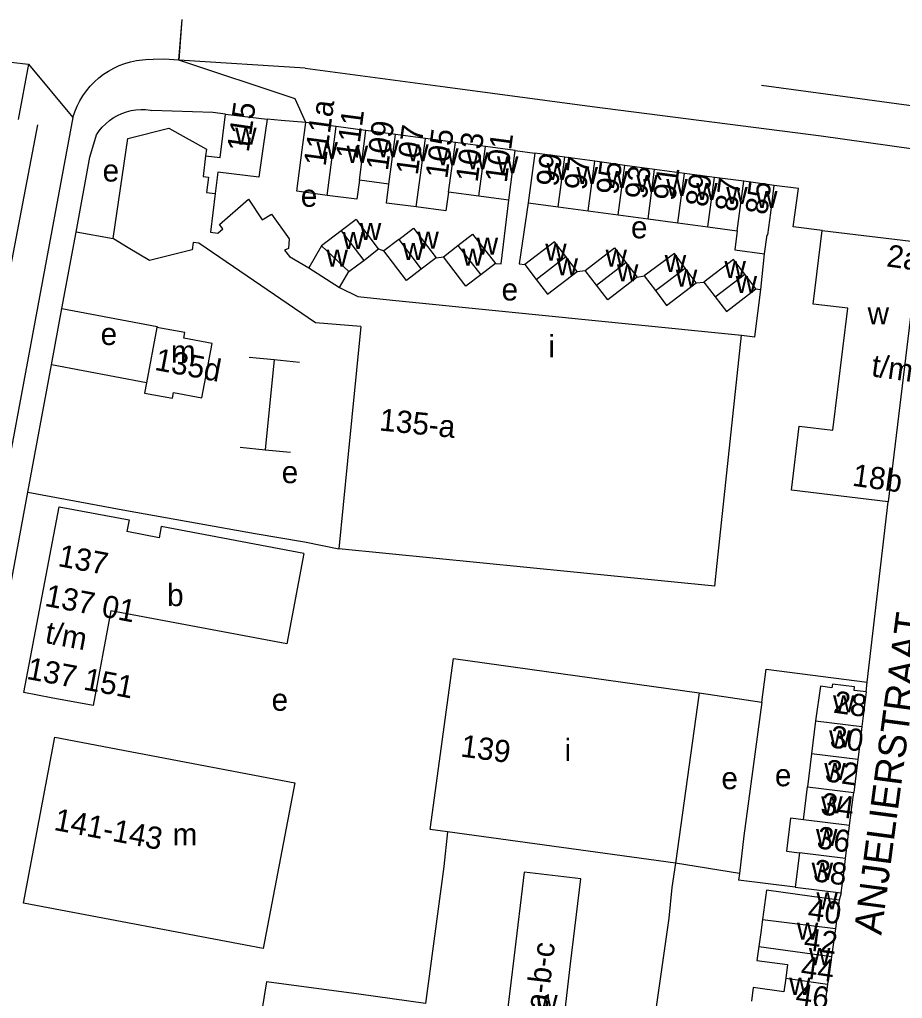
# Model space of a CAD drawing. Extents: x 161258 to 163262, y 380749 to 382054.
# Drawn here: x 161839.1 to 161998.1, y 381470.7 to 381647.1 of the extents above; entities that cross this region are included whole.
import ezdxf

# ---------------------------------------------------------------- set-up
doc = ezdxf.new("R2010")
doc.units = 0
for name, color, linetype in [('BLT_Basislijn', 7, 'Continuous'), ('BLT_Bebouwing', 7, 'Continuous'), ('BLT_Centroide', 7, 'Continuous'), ('BLT_Huisnummer', 7, 'Continuous'), ('BLT_Huisnummer_ tussenligend', 7, 'Continuous'), ('BLT_Huisnummer_reeks', 7, 'Continuous'), ('BLT_Onderverdeling_panden', 7, 'Continuous'), ('BLT_Straatnaam', 7, 'Continuous'), ('BLT_Vlakafsluiter', 7, 'Continuous')]:
    doc.layers.add(name, color=color, linetype=linetype)

msp = doc.modelspace()

# ---------------------------------------------------------------- linework, layer by layer
at = {"layer": 'BLT_Basislijn'}
for p, q in [((161865.19, 381639.93), (161863.15, 381639.92)), ((161867.69, 381639.77), (161865.19, 381639.93)), ((161867.74, 381639.77), (161867.69, 381639.77)), ((161890.5, 381638.33), (161867.74, 381639.77)), ((161848.67, 381629.43), (161829.26, 381525.22)), ((161886.18, 381628.93), (161883.71, 381629.14)), ((161890.62, 381628.56), (161886.18, 381628.93)), ((161928.39, 381623.47), (161931.92, 381622.99)), ((161983.65, 381609.07), (161978.46, 381609.76)), ((161846.7, 381595.04), (161849.25, 381608.8)), ((161855.92, 381607.61), (161849.25, 381608.8)), ((161903.77, 381605.76), (161904.72, 381605.42)), ((161914.13, 381604.18), (161915.43, 381604.36)), ((161972.63, 381598.47), (161973.31, 381604.89)), ((161939.52, 381601.72), (161940.95, 381601.89)), ((161950.37, 381600.65), (161951.59, 381600.92)), ((161960.99, 381599.65), (161962.38, 381599.78)), ((161971.54, 381589.91), (161972.63, 381598.47)), ((161971.73, 381598.55), (161972.63, 381598.47)), ((161844.82, 381584.89), (161846.7, 381595.04)), ((161969.13, 381590.24), (161971.54, 381589.91)), ((161840.57, 381561.92), (161844.82, 381584.89)), ((161880.44, 381586.28), (161884.97, 381585.82)), ((161884.97, 381585.82), (161883.35, 381569.58)), ((161884.97, 381585.82), (161889.51, 381585.37)), ((161878.8, 381570.03), (161883.35, 381569.58)), ((161883.35, 381569.58), (161887.88, 381569.12)), ((161991.81, 381527.74), (161995.59, 381560.22)), ((161972.82, 381524.14), (161973.56, 381530.03)), ((161973.56, 381530.03), (161991.81, 381527.74)), ((161961.49, 381525.82), (161972.82, 381524.14)), ((161968.77, 381493.27), (161957.23, 381495.12)), ((161968.77, 381493.27), (161968.62, 381492.02)), ((161978.81, 381490.77), (161968.62, 381492.02)), ((161987.12, 381489.74), (161986.76, 381488.41))]:
    msp.add_line(p, q, dxfattribs=at)
for points in [[(161848.67, 381629.43), (161849.02, 381630.46), (161849.43, 381631.46), (161849.92, 381632.42), (161850.48, 381633.34), (161851.11, 381634.23), (161851.8, 381635.06), (161852.55, 381635.84), (161853.36, 381636.56), (161854.21, 381637.22), (161855.11, 381637.81), (161856.06, 381638.34), (161857.04, 381638.79), (161858.05, 381639.17), (161859.09, 381639.48), (161860.14, 381639.71), (161861.21, 381639.86), (161862.29, 381639.93), (161863.15, 381639.92)], [(161890.62, 381628.56), (161888.74, 381632.82), (161867.74, 381639.77)], [(161837.52, 381639.39), (161840.71, 381639.08)], [(161840.71, 381639.08), (161838.84, 381629.11)], [(161890.5, 381638.33), (161915.74, 381634.98), (161942.21, 381631.45), (161983.51, 381626.15)], [(161972.76, 381635.24), (161986.51, 381633.39)], [(161986.51, 381633.39), (162033.24, 381627.05), (162058.66, 381624.22), (162070.84, 381623.16), (162081.43, 381622.63), (162093.08, 381622.28), (162119.5, 381621.62)], [(161852.95, 381626.31), (161853.43, 381627.04), (161853.98, 381627.71), (161854.59, 381628.33), (161855.25, 381628.9), (161855.96, 381629.4), (161856.72, 381629.83), (161857.51, 381630.19), (161858.33, 381630.48), (161859.18, 381630.69), (161860.04, 381630.83), (161860.91, 381630.88), (161861.78, 381630.86), (161862.64, 381630.75), (161862.88, 381630.71)], [(161876.17, 381630.06), (161873.92, 381630.32), (161862.88, 381630.71)], [(161787.91, 381344.08), (161804.27, 381430.36), (161834.23, 381585.88), (161842.37, 381628.14)], [(161849.25, 381608.8), (161851.74, 381622.31), (161852.95, 381626.31)], [(161983.51, 381626.15), (162038.53, 381618.39), (162049.65, 381617.33), (162066.6, 381615.74), (162081.96, 381614.86), (162104.2, 381614.33)], [(161978.46, 381609.76), (161979.39, 381616.68), (161975.04, 381617.22)], [(161924.81, 381603.15), (161925.85, 381603.05), (161927.2, 381614.54)], [(161930.72, 381614.07), (161929.11, 381603.08), (161930.12, 381602.97)], [(161846.7, 381595.04), (161863.84, 381591.81), (161863.8, 381591.63)], [(161861.95, 381581.66), (161844.82, 381584.89)], [(161821.19, 381474.73), (161830.92, 381509.79), (161840.57, 381561.92)], [(161840.57, 381561.92), (161858.34, 381558.67), (161881.51, 381554.51)], [(161881.51, 381554.51), (161890.39, 381553), (161896.59, 381551.76)], [(161991.58, 381525.98), (161991.81, 381527.74)], [(161972.82, 381524.14), (161969.58, 381500), (161968.77, 381493.27)], [(161916.15, 381500.72), (161915.53, 381494.51), (161912.22, 381469.83)], [(161957.23, 381495.12), (161956.61, 381490.71), (161956.07, 381485.21), (161949.07, 381436.37)]]:
    msp.add_lwpolyline(points, dxfattribs=at)
at = {"layer": 'BLT_Bebouwing'}
for p, q in [((161876.17, 381630.06), (161883.71, 381629.14)), ((161896.13, 381627.82), (161890.62, 381628.56)), ((161906.82, 381626.38), (161901.47, 381627.1)), ((161912.22, 381625.65), (161906.82, 381626.38)), ((161917.61, 381624.92), (161912.22, 381625.65)), ((161923, 381624.2), (161917.61, 381624.92)), ((161928.39, 381623.47), (161923, 381624.2)), ((161927.2, 381614.54), (161928.39, 381623.47)), ((161931.92, 381622.99), (161930.72, 381614.07)), ((161937.31, 381622.27), (161931.92, 381622.99)), ((161942.7, 381621.55), (161937.31, 381622.27)), ((161948.1, 381620.82), (161942.7, 381621.55)), ((161953.49, 381620.1), (161948.1, 381620.82)), ((161958.89, 381619.38), (161953.49, 381620.1)), ((161964.28, 381618.66), (161958.89, 381619.38)), ((161969.57, 381617.95), (161964.28, 381618.66)), ((161905.63, 381617.42), (161900.31, 381618.13)), ((161975.04, 381617.22), (161969.57, 381617.95)), ((161921.81, 381615.26), (161916.34, 381615.99)), ((161936.12, 381613.35), (161941.51, 381612.63)), ((161941.51, 381612.63), (161946.91, 381611.91)), ((161946.91, 381611.91), (161952.3, 381611.19)), ((161899.7, 381611.09), (161900, 381610.69)), ((161903.77, 381605.76), (161900, 381610.69)), ((161952.3, 381611.19), (161957.7, 381610.47)), ((161957.7, 381610.47), (161963.09, 381609.75)), ((161963.09, 381609.75), (161968.37, 381609.04)), ((161855.92, 381607.61), (161855.91, 381607.62)), ((161856, 381607.57), (161855.92, 381607.61)), ((161858.67, 381605.97), (161856, 381607.57)), ((161906.29, 381596.54), (161969.13, 381590.24)), ((161863.8, 381591.63), (161861.95, 381581.66)), ((161900.53, 381591.79), (161898.15, 381567.58)), ((161898.15, 381567.58), (161896.59, 381551.76)), ((161964.33, 381544.98), (161896.59, 381551.76)), ((161964.33, 381544.98), (161964.74, 381549.08)), ((161991.58, 381525.98), (161990.82, 381519.74)), ((161982.5, 381520.77), (161981.77, 381514.81)), ((161839.76, 381487.91), (161845.41, 381517.82)), ((161845.41, 381517.82), (161888.64, 381509.57)), ((161981.77, 381514.81), (161981.04, 381508.87)), ((161990.09, 381513.79), (161989.36, 381507.84)), ((161888.64, 381509.57), (161882.99, 381479.72)), ((161980.31, 381502.9), (161981.04, 381508.87)), ((161987.88, 381495.94), (161988.62, 381501.88)), ((161916.15, 381500.72), (161913.03, 381501.15)), ((161957.23, 381495.12), (161916.15, 381500.72)), ((161979.57, 381496.96), (161978.81, 381490.77)), ((161978.81, 381490.77), (161987.12, 381489.74)), ((161882.99, 381479.72), (161839.76, 381487.91)), ((161986.76, 381488.41), (161986.06, 381483.33)), ((161986.06, 381483.33), (161985.36, 381478.29)), ((161985.36, 381478.29), (161984.66, 381473.32)), ((161984.66, 381473.32), (161983.98, 381468.4))]:
    msp.add_line(p, q, dxfattribs=at)
for points in [[(161872.59, 381622.53), (161875.21, 381622.21), (161876.17, 381630.06)], [(161883.71, 381629.14), (161882.98, 381624.2), (161882.43, 381620.45)], [(161855.91, 381607.62), (161858.56, 381625.67), (161865.99, 381627.53), (161872.74, 381623.75), (161872.59, 381622.53)], [(161894.52, 381615.42), (161889.01, 381616.16), (161889.96, 381623.6), (161890.62, 381628.56)], [(161901.47, 381627.1), (161900, 381627.3), (161896.13, 381627.82)], [(161882.43, 381620.45), (161882.17, 381618.69), (161874.77, 381619.6), (161874.3, 381615.74)], [(161900.31, 381618.13), (161899.86, 381614.71), (161894.52, 381615.42)], [(161910.54, 381613.34), (161905.21, 381614.03), (161905.63, 381617.42)], [(161973.31, 381604.89), (161973.77, 381608.32), (161973.88, 381608.31), (161974.4, 381612.26), (161975.04, 381617.22)], [(161874.3, 381615.74), (161873.45, 381608.78), (161874.77, 381608.6), (161875.72, 381609.36), (161875.09, 381610.14), (161880.32, 381614.76), (161882.78, 381611), (161884.45, 381612.04), (161887.67, 381607.56), (161887.5, 381605.84), (161886.81, 381605.53), (161887.7, 381604.43), (161891.18, 381602.37)], [(161916.34, 381615.99), (161915.9, 381612.63), (161910.54, 381613.34)], [(161927.2, 381614.54), (161922.25, 381615.2), (161921.81, 381615.26)], [(161930.72, 381614.07), (161935.68, 381613.41), (161936.12, 381613.35)], [(161899.7, 381611.09), (161897.03, 381609.05)], [(161907.39, 381607.46), (161910.06, 381609.5), (161914.13, 381604.18)], [(161897.03, 381609.05), (161893.45, 381606.3)], [(161918.06, 381606.41), (161920.68, 381608.45), (161924.81, 381603.15)], [(161968.37, 381609.04), (161967.91, 381605.61), (161973.31, 381604.89)], [(161995.59, 381560.22), (161978.17, 381562.31), (161979.55, 381573.82), (161985.62, 381573.09), (161988.27, 381595.1), (161982.07, 381595.84), (161983.65, 381609.07)], [(161983.65, 381609.07), (162001.2, 381606.97), (161995.59, 381560.22)], [(161870.34, 381606.94), (161870.18, 381605.58), (161862.48, 381603.7), (161858.67, 381605.97)], [(161900.53, 381591.79), (161892.4, 381592.46), (161871.36, 381606.79), (161870.34, 381606.94)], [(161893.45, 381606.3), (161891.18, 381602.37)], [(161907.39, 381607.46), (161904.72, 381605.42)], [(161915.43, 381604.36), (161918.06, 381606.41)], [(161937.48, 381604.38), (161935.45, 381607.03), (161930.12, 381602.97)], [(161940.95, 381601.89), (161946.28, 381605.97), (161948.33, 381603.31)], [(161901.07, 381603.71), (161903.77, 381605.76)], [(161911.45, 381602.13), (161908.78, 381600.09), (161904.72, 381605.42)], [(161914.13, 381604.18), (161911.45, 381602.13)], [(161922.15, 381601.11), (161919.5, 381599.07), (161915.43, 381604.36)], [(161939.52, 381601.72), (161937.48, 381604.38)], [(161959.02, 381602.3), (161957.04, 381604.96), (161951.59, 381600.92)], [(161898.41, 381601.67), (161900, 381602.88), (161901.07, 381603.71)], [(161924.81, 381603.15), (161922.15, 381601.11)], [(161930.12, 381602.97), (161932.15, 381600.28)], [(161948.33, 381603.31), (161950.37, 381600.65)], [(161969.73, 381601.22), (161967.72, 381603.89), (161962.38, 381599.78)], [(161896.69, 381598.83), (161898.41, 381601.67)], [(161932.15, 381600.28), (161934.18, 381597.6), (161939.52, 381601.72)], [(161943.01, 381599.24), (161940.95, 381601.89)], [(161950.37, 381600.65), (161945.06, 381596.6), (161943.01, 381599.24)], [(161951.59, 381600.92), (161953.62, 381598.26)], [(161960.99, 381599.65), (161959.02, 381602.3)], [(161971.73, 381598.55), (161969.73, 381601.22)], [(161953.62, 381598.26), (161955.65, 381595.6), (161960.99, 381599.65)], [(161962.38, 381599.78), (161964.42, 381597.13)], [(161896.69, 381598.83), (161900, 381597.17), (161906.29, 381596.54)], [(161964.42, 381597.13), (161966.46, 381594.49), (161971.73, 381598.55)], [(161861.95, 381581.66), (161861.6, 381579.8), (161866.6, 381578.87), (161866.78, 381579.87), (161871.94, 381578.91), (161873.77, 381588.75), (161868.67, 381589.69), (161868.86, 381590.69), (161863.8, 381591.63)], [(161964.74, 381549.08), (161969.13, 381590.24)], [(161855.53, 381540.57), (161852.32, 381523.5), (161844.74, 381524.92), (161839.83, 381525.85), (161846.23, 381559.33), (161858.8, 381556.96), (161858.4, 381554.83)], [(161890.3, 381550.89), (161864.59, 381555.73), (161864.21, 381553.74), (161858.4, 381554.83)], [(161890.3, 381550.89), (161887.23, 381534.6), (161855.53, 381540.57)], [(161913.03, 381501.15), (161917.27, 381531.95), (161961.49, 381525.82)], [(161991.58, 381525.98), (161989.41, 381526.24), (161989.49, 381526.9), (161985.52, 381527.37), (161985.44, 381526.72), (161983.35, 381526.97), (161982.5, 381520.77)], [(161961.49, 381525.82), (161957.23, 381495.12)], [(161990.82, 381519.74), (161990.56, 381517.55), (161990.09, 381513.79)], [(161988.62, 381501.88), (161989.09, 381505.66), (161989.36, 381507.84)], [(161980.31, 381502.9), (161977.97, 381503.19), (161977.24, 381497.25), (161979.57, 381496.96)], [(161987.12, 381489.74), (161987.62, 381493.74), (161987.88, 381495.94)], [(161938.36, 381476.95), (161940.18, 381492.3), (161929.97, 381493.51), (161928.12, 381478)], [(161986.76, 381488.41), (161981.81, 381489.1), (161973.63, 381490.24), (161972.95, 381484.93)], [(161972.95, 381484.93), (161972.63, 381482.64), (161972.28, 381480.11)], [(161972.28, 381480.11), (161971.93, 381477.59), (161977.45, 381476.82), (161977.11, 381474.38)], [(161928.12, 381478), (161926.53, 381464.67), (161925.94, 381459.71), (161936.16, 381458.49), (161936.76, 381463.46)], [(161936.76, 381463.46), (161938.36, 381476.95)], [(161912.22, 381469.83), (161900.22, 381471.49), (161883.58, 381473.74), (161878.29, 381441.24)], [(161977.11, 381474.38), (161976.77, 381471.93), (161971.26, 381472.7), (161970.92, 381470.22)]]:
    msp.add_lwpolyline(points, dxfattribs=at)
at = {"layer": 'BLT_Onderverdeling_panden'}
for p, q in [((161894.52, 381615.42), (161896.13, 381627.82)), ((161900.31, 381618.13), (161901.47, 381627.1)), ((161905.63, 381617.42), (161906.82, 381626.38)), ((161910.54, 381613.34), (161912.22, 381625.65)), ((161916.34, 381615.99), (161917.61, 381624.92)), ((161921.81, 381615.26), (161923, 381624.2)), ((161936.12, 381613.35), (161937.31, 381622.27)), ((161941.51, 381612.63), (161942.7, 381621.55)), ((161946.91, 381611.91), (161948.1, 381620.82)), ((161952.3, 381611.19), (161953.49, 381620.1)), ((161957.7, 381610.47), (161958.89, 381619.38)), ((161963.09, 381609.75), (161964.28, 381618.66)), ((161968.37, 381609.04), (161969.57, 381617.95)), ((161897.03, 381609.05), (161901.07, 381603.71)), ((161893.45, 381606.3), (161898.41, 381601.67)), ((161907.39, 381607.46), (161911.45, 381602.13)), ((161918.06, 381606.41), (161922.15, 381601.11)), ((161932.15, 381600.28), (161937.48, 381604.38)), ((161943.01, 381599.24), (161948.33, 381603.31)), ((161891.18, 381602.37), (161896.69, 381598.83)), ((161953.62, 381598.26), (161959.02, 381602.3)), ((161964.42, 381597.13), (161969.73, 381601.22)), ((161982.5, 381520.77), (161990.82, 381519.74)), ((161990.09, 381513.79), (161981.77, 381514.81)), ((161981.04, 381508.87), (161989.36, 381507.84)), ((161988.62, 381501.88), (161980.31, 381502.9)), ((161987.88, 381495.94), (161979.57, 381496.96)), ((161972.95, 381484.93), (161986.06, 381483.33)), ((161972.28, 381480.11), (161985.36, 381478.29)), ((161977.11, 381474.38), (161984.66, 381473.32))]:
    msp.add_line(p, q, dxfattribs=at)
msp.add_lwpolyline([(161872.59, 381622.53), (161872.13, 381618.84), (161873.11, 381618.7), (161872.73, 381615.96), (161874.3, 381615.74)], dxfattribs=at)
at = {"layer": 'BLT_Vlakafsluiter'}
for p, q in [((161868.28, 381647.08), (161867.69, 381639.77)), ((161868.33, 381647.08), (161867.74, 381639.77)), ((161840.71, 381639.08), (161848.67, 381629.43))]:
    msp.add_line(p, q, dxfattribs=at)

# ---------------------------------------------------------------- texts
at = {"layer": 'BLT_Centroide'}
for s, p in [('w', (161877.92, 381624.53)), ('w', (161903.56, 381622.25)), ('w', (161892.56, 381621.98)), ('w', (161898, 381621.27)), ('w', (161908.92, 381621.53)), ('w', (161914.31, 381620.81)), ('w', (161919.7, 381620.09)), ('w', (161925.09, 381619.36)), ('e', (161854.04, 381617.9)), ('w', (161934.02, 381618.17)), ('w', (161939.41, 381617.45)), ('w', (161944.81, 381616.72)), ('w', (161950.2, 381616)), ('w', (161955.59, 381615.28)), ('w', (161960.98, 381614.56)), ('w', (161966.39, 381613.84)), ('e', (161889.74, 381613.36)), ('w', (161971.77, 381613.12)), ('w', (161900.39, 381607.39)), ('e', (161949.23, 381607.67)), ('w', (161897.27, 381605.75)), ('w', (161910.75, 381605.81)), ('w', (161921.44, 381604.75)), ('w', (161908.08, 381603.77)), ('w', (161933.78, 381603.66)), ('w', (161894.37, 381602.56)), ('w', (161918.8, 381602.73)), ('w', (161944.65, 381602.59)), ('w', (161955.31, 381601.59)), ('w', (161935.82, 381601)), ('w', (161946.7, 381599.94)), ('w', (161966.07, 381600.5)), ('w', (161957.31, 381598.94)), ('w', (161968.09, 381597.84)), ('e', (161925.91, 381596.48)), ('w', (161991.86, 381592.19)), ('e', (161853.68, 381588.45)), ('i', (161934.34, 381586.25)), ('m', (161866.35, 381585.3)), ('e', (161886.3, 381563.56)), ('b', (161865.66, 381541.41)), ('e', (161884.48, 381522.56)), ('w', (161985.63, 381522.29)), ('i', (161937.26, 381513.53)), ('w', (161984.92, 381515.99)), ('w', (161984.05, 381510.08)), ('e', (161965.52, 381508.43)), ('e', (161975.16, 381508.96)), ('w', (161983.5, 381504.06)), ('m', (161866.65, 381498.31)), ('w', (161982.56, 381498.17)), ('w', (161981.78, 381492.1)), ('w', (161982.64, 381486.78)), ('w', (161979.12, 381481.34)), ('w', (161981.29, 381476.72)), ('w', (161977.73, 381471.38)), ('w', (161932.16, 381468.28))]:
    msp.add_text(s, height=4, dxfattribs=at).set_placement(p)
at = {"layer": 'BLT_Huisnummer'}
for s, rotation, p in [('111a', 82.397, (161894.21, 381620.54)), ('115', 81.6268, (161880.36, 381623.08)), ('111', 82.3974, (161899.98, 381621.8)), ('105', 82.3974, (161916.13, 381618.29)), ('101', 82.4372, (161926.84, 381617.57)), ('99', 82.3995, (161936.06, 381616.87)), ('93', 82.3978, (161952.04, 381614.59)), ('89', 82.3982, (161962.99, 381613.2)), ('85', 82.5765, (161973.76, 381611.8)), ('135d', 349.4004, (161863.26, 381583.99)), ('28', 352, (161985.55, 381522.24)), ('30', 352, (161984.92, 381515.99)), ('139', 352.2292, (161918.39, 381514.34)), ('34', 352, (161983.24, 381503.91)), ('38', 352, (161981.93, 381491.89)), ('42', 352.0726, (161980.23, 381479.53)), ('46', 352.0702, (161978.73, 381469.58))]:
    msp.add_text(s, height=4, rotation=rotation, dxfattribs=at).set_placement(p)
at = {"layer": 'BLT_Huisnummer_ tussenligend'}
for s, rotation, p in [('109', 82.397, (161905.43, 381619.74)), ('107', 82.3974, (161910.81, 381618.96)), ('103', 82.4372, (161921.59, 381617.67)), ('97', 82.3978, (161941.13, 381616.22)), ('95', 82.3978, (161946.86, 381615.41)), ('91', 82.3982, (161957.19, 381614.33)), ('87', 82.5765, (161968.3, 381612.33)), ('32', 352, (161984.04, 381509.89)), ('36', 352, (161982.55, 381497.82)), ('40', 352.0835, (161980.92, 381484.87)), ('44', 352.0726, (161979.67, 381474.48))]:
    msp.add_text(s, height=4, rotation=rotation, dxfattribs=at).set_placement(p)
at = {"layer": 'BLT_Huisnummer_reeks'}
for s, rotation, p in [('2a', 352, (161995.14, 381602.64)), ('t/m', 352, (161992.4, 381582.84)), ('135-a', 354.28, (161903.77, 381573.07)), ('18b', 352, (161988.95, 381563.12)), ('137', 349.4004, (161845.83, 381548.65)), ('137 01', 349.4004, (161843.45, 381541.47)), ('t/m', 349.4004, (161843.5, 381534.81)), ('137 151', 349.4004, (161840.19, 381528.32)), ('141-143', 349.288, (161845.11, 381501.11)), ('34-a-b-c', 83.2005, (161933.2, 381460.86))]:
    msp.add_text(s, height=4, rotation=rotation, dxfattribs=at).set_placement(p)
at = {"layer": 'BLT_Straatnaam'}
msp.add_text('ANJELIERSTRAAT', height=5, rotation=82.425, dxfattribs=at).set_placement((161994.32, 381482.04))

doc.saveas('drawing.dxf')
